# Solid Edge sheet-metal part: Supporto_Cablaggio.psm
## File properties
Author: f_grande
Template: Normal.psm
Last saved by: f_grande
Revision: 6
Application: Solid Edge
Density: 7833,000 kg/m^3
Accuracy: 0,990
Material Thickness: 2,00 mm
Bend Radius: 1,00 mm
Relief Width: 1,00 mm
Relief Length: 0,00 mm
Neutral Factor: 0,330
Minimum Arc Length: 0,10 mm
Deviational Tolerance: 0,10 mm
Tipo di contenuto documento: 0
Material: Acciaio galvanizzato
Stile della faccia: Acciaio
Stile di riempimento: ANSI32(Acciaio)
Stile virtuale: Galvanizzato
Coef. of Thermal Exp: 0.0
Thermal Conductivity: 32.0
Specific Heat: 481.0
Modulus of Elasticity: 199947953000.0
Poisson's Ratio: 0.29
Yield Stress: 262000766.0
Ultimate Stress: 358527364.0
Elongation: 0.0
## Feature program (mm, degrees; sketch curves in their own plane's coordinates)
base tab "unnamed BaseTab 1"
sketch for "unnamed Hole 1" plane through (11.9785, 1.2029, 2) normal (0, 0, 1) x-axis (1, 0, 0)
  hole centre (11.5915, 22.3671) bore radius 2.25
hole "unnamed Hole 1"
sketch for "unnamed Hole 2" plane through (11.9785, 1.2029, 2) normal (0, 0, 1) x-axis (1, 0, 0)
  hole centre (11.5915, -24.7729) bore radius 2.25
hole "unnamed Hole 2"
sketch for "unnamed Hole 3" plane through (11.9785, 1.2029, 2) normal (0, 0, 1) x-axis (1, 0, 0)
  hole centre (-35.5485, -24.7729) bore radius 2.25
hole "unnamed Hole 3"
sketch for "unnamed Hole 4" plane through (11.9785, 1.2029, 2) normal (0, 0, 1) x-axis (1, 0, 0)
  hole centre (-35.5485, 22.3671) bore radius 2.25
  dimension (linear) = 35.5485
hole "unnamed Hole 4"
pattern "unnamed Pattern 1" of "unnamed Hole 1", "unnamed Hole 2", "unnamed Hole 3", "unnamed Hole 4"
sketch for "Foro_5" plane through (0, 0, 2) normal (0, 0, 1) x-axis (1, 0, 0)
  hole centre (0, 0) bore radius 5
hole "Foro_5"
flange "Lembo_3"
sketch for "Foro_7" plane through (0, -55.6638, 14.3529) normal (0, -0.5, -0.866025) x-axis (1, 0, 0)
  hole centre (0, 1.9641) bore radius 10
hole "Foro_7"
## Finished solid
Body 1: solid body, 16 faces, 36 edges, 16 vertices.
  Faces by surface: cylinder 8, plane 8
  Edges by curve: line 20, circle 16
Bounding box of the edges (mm): 60.000 x 113.230 x 32.000, from (-30, -83.2295, 0) to (30, 30, 32).
Cylindrical faces by radius (mm): R1 x1, R2.25 x4, R3 x1, R5 x1, R10 x1
Planar faces by outward normal: +x 1, +y 1, +z 1, -x 1, -z 1, oblique 3
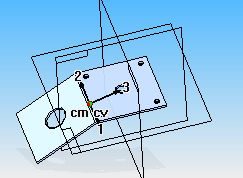
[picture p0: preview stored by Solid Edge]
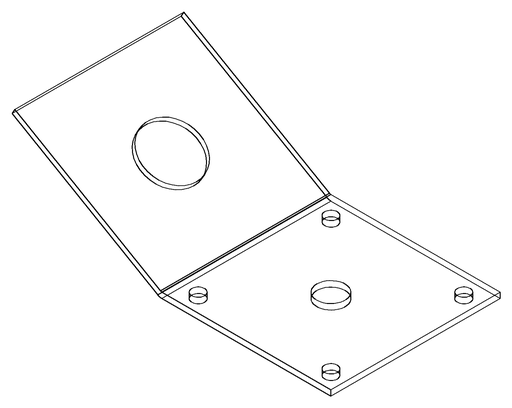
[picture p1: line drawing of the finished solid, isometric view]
